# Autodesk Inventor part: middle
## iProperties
Shininess: 64.0
Length Units: 11269
Angle Units: 11279
Time Units: 11290
Mass Units: 11283
Length Display Precision: 3
Angle Display Precision: 2
Compacted: True
Part Number: middle
Document SubType Name: Modeling
Created: 2004-10
Material: Standard
Designer: W. Holzwarth
Manufacturer: Standard
Standards Organization: Custom
Density: 0.0
Volumn: 0.0
Area: 0.0
PropertySet Name: Model Information
Control State: 0
Master: False
Checked Out: False
Author: W. Holzwarth
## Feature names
1. Basis1
